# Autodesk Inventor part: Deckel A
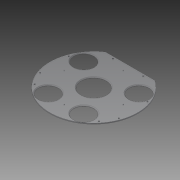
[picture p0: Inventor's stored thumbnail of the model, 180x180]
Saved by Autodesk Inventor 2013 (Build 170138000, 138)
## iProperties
Created: 2012-10
Part Number: Deckel A
Material: PMMA-Kunststoff
Document SubType Name: Modeling
Designer: SteffenHaase
Density: 1.188 g/cm^3
Mass: 66.6879 g
Surface Area: 407.346 cm^2
Volume: 56.1346 cm^3
Author: SteffenHaase
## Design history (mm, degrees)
sketch "Skizze1"
  geometry: L1 (-48.836, 72)-(48.836, 72); A1 r 87 centre (0, 0) between (-48.836, 72) and (48.836, 72); 1 further point
  constraints: 2 end point, 2 point on circle, 1 centre point, 1 coincident, 1 horizontal
  dimensions: "d2" = 174 diameter of A1; "d3" = 72 distance from line of point (0, 0) L1
extrude "Extrusion1" new body sketch "Skizze1" distance "d5" = 2; taper "d6" = 0 deg
sketch "Skizze2"
  geometry: L1 (-121.8, 0)-(121.8, 0) reference; L2 (0, -118.8)-(0, 103.8) reference; C1 r 25 at (0, 0); C2 r 20 at (-54.772, 35); C3 r 20 at (54.772, 35); C4 r 20 at (35, -54.772); C5 r 20 at (-35, -54.772); A1 r 87 centre (0, 0) between (-48.836, 72) and (48.836, 72) reference
  constraints: 5 centre point, 1 coincident
  dimensions: "d57" = 50 diameter of C1; "d59" = 35 distance from line of C2.centre L1; "d60" = 35 distance from line of L1 C3.centre (= d59); "d61" = 54.772 distance from line of C2.centre L2; "d62" = 40 diameter of C2; "d63" = 54.772 distance from line of C3.centre L2 (= d61); "d64" = 54.772 distance from line of C4.centre L1 (= d61); "d65" = 35 distance from line of L2 C4.centre (= d59); "d66" = 54.772 distance from line of C5.centre L1 (= d61); "d67" = 35 distance from line of L2 C5.centre (= d59); "d68" = 40 diameter of C5 (= d62); "d69" = 40 diameter of C3 (= d62); "d70" = 40 diameter of C4 (= d62)
extrude "Extrusion2" cut sketch "Skizze2" stored distance "d7" = 3; taper "d8" = 0 deg
sketch "Skizze6"
  geometry: L1 (0, 0)-(-63.582, -53.351); L2 (0, 0)-(63.582, -53.351); L3 (-121.8, 0)-(121.8, 0) reference; L4 (-30, 68)-(30, 68); L5 (0, 117)-(0, -121) reference; A1 r 87 centre (0, 0) between (-48.836, 72) and (48.836, 72) reference; A2 r 83 centre (0, 0) between (-63.582, -53.351) and (63.582, -53.351); 4 further points
  constraints: 6 end point, 5 coincident, 2 point on circle, 1 centre point, 1 parallel, 1 symmetric about line
  dimensions: "d72" = 166 diameter of A2; "d73" = 40 deg angle of L3 L1; "d75" = 40 deg angle of L2 L3 (= d73); "d77" = 60 distance of L4.start L4.end; "d78" = 68 distance between parallel lines of L3 L4
hole "Bohrung4" sketch "Skizze6" at (-63.582, -53.351), (63.582, -53.351), (-30, 68), (30, 68) diameter "d79" = 2.459; stored, may be unused: countersink angle "d83" = 90 deg, drill point angle "d85" = 118 deg; dims "d80" = 6, "d81" = 4, "d82" = 2, "d84" = 8
chamfer "Fase2" distance "d86" = 1.5; stored, may be unused: second distance "d87" = 2, angle "d88" = 45 deg
sketch "Skizze7"
  geometry: L1 (-121.8, 0)-(121.8, 0) reference; L2 (0, 103.8)-(0, -118.8) reference; 3 further points
  constraints: 2 point on line, 1 symmetric about line
  dimensions: "d89" = 160 distance of point (80, 0) point (-80, 0)
hole "Bohrung5" sketch "Skizze7" at (-80, 0), (80, 0) diameter "d90" = 3.2; stored, may be unused: countersink angle "d94" = 90 deg, drill point angle "d96" = 118 deg; dims "d91" = 6, "d92" = 4, "d93" = 2, "d95" = 8
node "Volumenkörper1"
